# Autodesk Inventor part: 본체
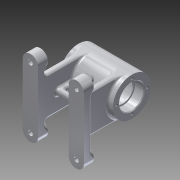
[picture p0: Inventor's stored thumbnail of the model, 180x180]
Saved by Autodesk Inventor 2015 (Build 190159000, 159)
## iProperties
Created: 2015-11
Part Number: 본체
Material: 알루미늄 6061
Document SubType Name: Modeling
Designer: Administrator
Density: 2.7 g/cm^3
Appearance: 알루미늄 - 평지
Mass: 356.441 g
Surface Area: 456.522 cm^2
Volume: 132.015 cm^3
Author: Administrator
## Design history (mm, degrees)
sketch "스케치1"
  geometry: L1 (40, 40)-(40, -40); L2 (20, 40)-(20, -40); L3 (-20, 40)-(-20, -40); L4 (-40, 40)-(-40, -40); A1 r 10 centre (30, 40) between (40, 40) and (20, 40); A2 r 10 centre (30, -40) between (40, -40) and (20, -40); A3 r 10 centre (-30, 40) between (-20, 40) and (-40, 40); A4 r 10 centre (-30, -40) between (-20, -40) and (-40, -40); 3 further points
  constraints: 8 end point, 8 point on circle, 4 centre point, 3 vertical, 1 horizontal alignment, 1 tangent, 1 vertical alignment
  dimensions: "d2" = 20 diameter of A1; "d3" = 20 diameter of A2; "d4" = 20 diameter of A3; "d5" = 20 diameter of A4
extrude "돌출1" new body sketch "스케치1" distance "d6" = 10; taper "d7" = 0 deg
sketch "스케치2"
  geometry: L1 (-20, -40)-(-20, 40) reference; L2 (-40, 40)-(-40, -40) reference; C1 r 10 at (-30, -40); C2 r 10 at (-30, 40); A1 r 10 centre (-30, -40) between (-40, -40) and (-20, -40) reference; A2 r 10 centre (-30, 40) between (-20, 40) and (-40, 40) reference; 1 further point
  constraints: 2 centre point, 2 coincident
  dimensions: "d8" = 20 diameter of C1; "d9" = 20 diameter of C2
extrude "돌출2" join sketch "스케치2" distance "d10" = 3; taper "d11" = 0 deg
sketch "스케치3"
  geometry: L1 (20, 40)-(20, -40) reference; L2 (40, -40)-(40, 40) reference; C1 r 10 at (30, -40); C2 r 10 at (30, 40); A1 r 10 centre (30, 40) between (40, 40) and (20, 40) reference; A2 r 10 centre (30, -40) between (20, -40) and (40, -40) reference; 1 further point
  constraints: 2 centre point, 2 coincident
  dimensions: "d12" = 20 diameter of C1; "d13" = 20 diameter of C2
extrude "돌출3" join sketch "스케치3" distance "d14" = 3; taper "d15" = 0 deg
node "작업 평면1"
sketch "스케치4"
  geometry: L1 (0, 0)-(80, 0) reference; L2 (40, 0)-(40, 68); C1 r 25 at (40, 68)
  constraints: 2 end point, 1 centre point, 1 coincident, 1 vertical
  dimensions: "d16" = 68 distance of L2.start L2.end; "d17" = 50 diameter of C1
extrude "돌출4" join sketch "스케치4" stored distance "d18" = 70; taper "d19" = 0 deg
node "작업 평면2"
sketch "스케치5"
  geometry: C1 r 5 at (0, 0); 1 further point
  constraints: 1 centre point, 1 coincident
  dimensions: "d20" = 10 diameter of C1
extrude "돌출5" join sketch "스케치5" distance "d21" = 3; taper "d23" = 0 deg; dims "d22" = 3, "d24" = 0
sketch "스케치6"
  geometry: L1 (35, 43)-(35, 93) reference; L2 (35, 68)-(-35, 68); L3 (-35, 93)-(-35, 43) reference; L4 (-35, 84)-(-23.3, 84); L5 (-23, 83.7)-(-23, 82); L6 (35, 84)-(23.3, 84); L7 (23, 83.7)-(23, 82); L8 (0, 68)-(-21, 68); L9 (-21, 82)-(-21, 86); L10 (-18, 89)-(18, 89); L11 (21, 86)-(21, 82); L12 (-21, 82)-(-23, 82); L13 (21, 82)-(23, 82); A1 r 3 centre (-18, 86) between (-18, 89) and (-21, 86); A2 r 3 centre (18, 86) between (21, 86) and (18, 89); A3 r 0.3 centre (-23.3, 83.7) between (-23, 83.7) and (-23.3, 84); A4 r 0.3 centre (23.3, 83.7) between (23.3, 84) and (23, 83.7); 1 further point
  constraints: 22 end point, 8 point on circle, 8 tangent, 7 perpendicular, 4 centre point, 3 midpoint, 3 point on line, 2 equal radius
  dimensions: "d34" = 3 radius of A1; "d35" = 0.3 radius of A3
revolve "회전1" sketch "스케치6" stored, may be unused: angle "d36" = 90 deg
chamfer "모따기1" distance "d37" = 1; stored, may be unused: second distance "d38" = 2, angle "d39" = 45 deg
node "작업 평면3"
sketch "스케치7"
  geometry: L1 (40, -40)-(40, 40) reference; L2 (20, 40)-(20, -40) reference; L3 (-40, 40)-(-40, -40) reference; L4 (-20, -40)-(-20, 40) reference; L5 (20, 0)-(20, -25); L6 (20, -25)-(28, -25); L7 (28, -25)-(28, 25); L8 (28, 25)-(20, 25); L9 (20, 25)-(20, 0); L10 (20, 40)-(20, -40) reference; L11 (-20, 0)-(-20, -25); L12 (-20, -40)-(-20, 40) reference; L13 (-20, -25)-(-28, -25); L14 (-28, -25)-(-28, 25); L15 (-28, 25)-(-20, 25); L16 (-20, 25)-(-20, 0); A1 r 10 centre (30, 40) between (40, 40) and (20, 40) reference; A2 r 10 centre (30, -40) between (20, -40) and (40, -40) reference; A3 r 10 centre (-30, -40) between (-40, -40) and (-20, -40) reference; A4 r 10 centre (-30, 40) between (-20, 40) and (-40, 40) reference; 1 further point
  constraints: 20 end point, 6 perpendicular, 4 point on line, 2 collinear, 2 midpoint
  dimensions: "d42" = 25 distance of L5.start L5.end; "d43" = 8 distance of L5.end L6.end; "d44" = 50 distance of L6.end L7.end; "d45" = 25 distance of L11.start L11.end; "d46" = 8 distance of L11.end L13.end; "d47" = 50 distance of L13.end L14.end
extrude "돌출6" join sketch "스케치7" stored distance "d48" = 3; taper "d49" = 0 deg
sketch "스케치8"
  geometry: L1 (40, 23)-(44, 23); L2 (40, 23)-(36, 23); L3 (36, 23)-(36, 43.322); L4 (44, 23)-(44, 43.322); A1 r 25 centre (40, 68) between (15, 68) and (65, 68) reference; 1 further point
  constraints: 8 end point, 2 horizontal, 2 point on circle, 2 vertical
extrude "돌출7" join sketch "스케치8" stored distance "d53" = 3; taper "d54" = 0 deg
sketch "스케치9"
  geometry: L1 (8.5, 13.5)-(31.5, 13.5); L2 (8.5, 6.5)-(31.5, 6.5); A1 r 3.5 centre (8.5, 10) between (8.5, 13.5) and (8.5, 6.5); A2 r 3.5 centre (31.5, 10) between (31.5, 6.5) and (31.5, 13.5); 1 further point
  constraints: 4 end point, 4 point on circle, 2 centre point, 1 horizontal, 1 tangent
  dimensions: "d58" = 7 diameter of A1; "d59" = 7 diameter of A2
extrude "돌출8" cut sketch "스케치9" distance "d60" = 8; taper "d61" = 0 deg
node "작업 평면4"
sketch "스케치11"
  geometry: C1 r 6 at (0, 0); 1 further point
  constraints: 1 centre point
  dimensions: "d65" = 12 diameter of C1
extrude "돌출10" join sketch "스케치11" distance "d66" = 3; taper "d67" = 0 deg
sketch "스케치12"
  geometry: C1 r 0.524 at (0, 0); 1 further point
  constraints: 1 centre point, 1 coincident
hole "구멍1" sketch "스케치12" at (0, 0) diameter "d68" = 5.188; stored, may be unused: countersink angle "d72" = 90 deg, drill point angle "d74" = 118 deg; dims "d69" = 12, "d70" = 4, "d71" = 2, "d73" = 25
sketch "스케치13"
  geometry: C1 r 0.6 at (0, 0); 1 further point
  constraints: 1 centre point
hole "구멍2" sketch "스케치13" at (0, 0) diameter "d75" = 5.188; stored, may be unused: countersink angle "d79" = 90 deg, drill point angle "d81" = 118 deg; dims "d76" = 12, "d77" = 4, "d78" = 2, "d80" = 25
sketch "스케치14"
  geometry: L1 (0, 0)-(0, 20); L2 (0, 0)-(20, 0); L3 (0, -0.509)-(0, -20); L4 (0, 0)-(-20, 0); A1 r 20 centre (0, 0) between (0, 20) and (20, 0); 1 further point
  constraints: 8 end point, 4 point on circle, 2 horizontal, 1 centre point, 1 vertical
hole "구멍3" sketch "스케치14" at (0, 20), (-20, 0), (0, -20), (20, 0) diameter "d83" = 3.242; stored, may be unused: countersink angle "d87" = 90 deg, drill point angle "d89" = 118 deg; dims "d84" = 8, "d85" = 4, "d86" = 2, "d88" = 10
sketch "스케치15"
  geometry: C1 r 10 at (0, 0) reference; C2 r 6 at (0, 0); 1 further point
  constraints: 1 centre point, 1 coincident
  dimensions: "d90" = 12 diameter of C2
extrude "돌출11" cut sketch "스케치15" distance "d91" = 4; taper "d92" = 0 deg
sketch "스케치16"
  geometry: L1 (-40, -40)-(-40, 40) reference; L2 (-20, 40)-(-20, -40) reference; C1 r 3 at (-30, 40); A1 r 10 centre (-30, 40) between (-20, 40) and (-40, 40) reference; A2 r 10 centre (-30, -40) between (-40, -40) and (-20, -40) reference; 1 further point
  constraints: 1 centre point, 1 coincident
  dimensions: "d93" = 6 diameter of C1
extrude "돌출12" cut sketch "스케치16" distance "d94" = 10; taper "d95" = 0 deg
fillet "모깎기1" dims "d96" = 3.5
fillet "모깎기2" dims "d97" = 3
fillet "모깎기3" dims "d98" = 3
fillet "모깎기4" dims "d99" = 3
fillet "모깎기5" dims "d100" = 3
fillet "모깎기6" dims "d101" = 3
fillet "모깎기7" dims "d102" = 3
fillet "모깎기8" dims "d103" = 3
fillet "모깎기9" dims "d104" = 3
fillet "모깎기10" dims "d105" = 3
node "작업 평면5"
sketch "스케치17"
  geometry: L1 (-35, 25)-(-35, -25) reference; 3 further points
  constraints: 1 horizontal alignment, 1 midpoint, 1 vertical alignment, 1 other
feature "엠보싱1" sketch "스케치17" dims "d9" = 20, "d106" = 0.5, "d107" = 0
fillet "모깎기11" dims "d108" = 3
fillet "모깎기12" dims "d109" = 0.3
node "솔리드1"
mirror "대칭1"
mirror "대칭2"
mirror "대칭3"
node "투영된 루프1"
node "투영된 루프2"
node "투영된 루프3"
node "투영된 루프4"
node "투영된 루프5"
node "투영된 루프6"
